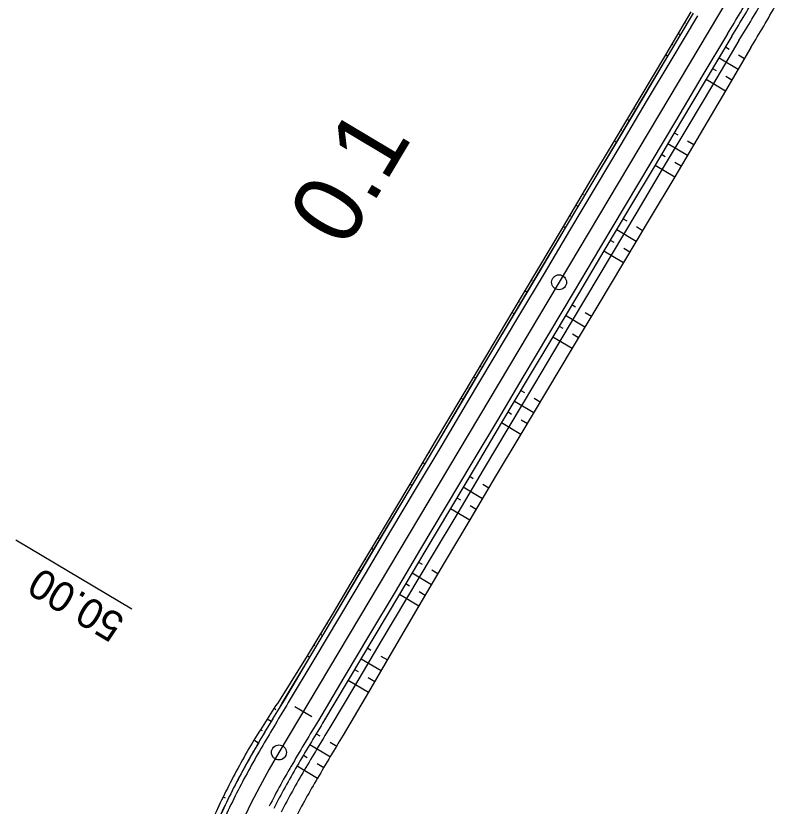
# Model space of a CAD drawing. Extents: x -481656 to -478728, y -1113199 to -1110710.
# Drawn here: x -479546.1 to -479469.9, y -1112507.3 to -1112428.2 of the extents above; entities that cross this region are included whole.
import ezdxf

# ---------------------------------------------------------------- set-up
doc = ezdxf.new("R2010")
doc.units = 0
for name, color, linetype in [('C1_HATCH_SLOPE_L', 7, 'Continuous'), ('C1_HATCH_SLOPE_R', 7, 'Continuous'), ('C1_HECTOMETRY', 7, 'Continuous'), ('C1_HLBODY', 7, 'Continuous'), ('C1_HRANA_TELESO', 7, 'Continuous'), ('C1_KORUNA', 7, 'Continuous'), ('C1_OSA', 7, 'Continuous'), ('C1_PRIKOP', 7, 'Continuous'), ('C1_STANICENI', 7, 'Continuous'), ('C1_VOZOVKA', 7, 'Continuous'), ('C1_ZPEVKRAJ', 7, 'Continuous')]:
    doc.layers.add(name, color=color, linetype=linetype)

msp = doc.modelspace()

# ---------------------------------------------------------------- linework, layer by layer
at = {"layer": 'C1_HATCH_SLOPE_L'}
for p, q in [((-479475.03, -1112431.371), (-479474.67, -1112431.586)), ((-479475.67, -1112432.445), (-479473.754, -1112433.587)), ((-479473.715, -1112432.154), (-479473.12, -1112432.509)), ((-479476.31, -1112433.519), (-479475.95, -1112433.734)), ((-479476.95, -1112434.593), (-479475.022, -1112435.741)), ((-479474.989, -1112434.306), (-479474.388, -1112434.664)), ((-479480.149, -1112439.962), (-479479.79, -1112440.176)), ((-479480.789, -1112441.036), (-479478.833, -1112442.201)), ((-479478.813, -1112440.758), (-479478.196, -1112441.126)), ((-479481.429, -1112442.109), (-479481.069, -1112442.324)), ((-479482.069, -1112443.183), (-479480.108, -1112444.352)), ((-479480.09, -1112442.908), (-479479.47, -1112443.277)), ((-479485.268, -1112448.552), (-479484.908, -1112448.766)), ((-479485.908, -1112449.626), (-479483.955, -1112450.79)), ((-479483.931, -1112449.349), (-479483.314, -1112449.717)), ((-479486.548, -1112450.7), (-479486.188, -1112450.914)), ((-479485.212, -1112451.496), (-479484.596, -1112451.863)), ((-479487.188, -1112451.774), (-479485.237, -1112452.936)), ((-479490.387, -1112457.143), (-479490.027, -1112457.357)), ((-479491.027, -1112458.217), (-479489.084, -1112459.375)), ((-479489.056, -1112457.936), (-479488.443, -1112458.301)), ((-479491.667, -1112459.29), (-479491.307, -1112459.504)), ((-479490.336, -1112460.084), (-479489.725, -1112460.448)), ((-479492.307, -1112460.364), (-479490.366, -1112461.521)), ((-479495.506, -1112465.733), (-479495.146, -1112465.948)), ((-479494.179, -1112466.524), (-479493.571, -1112466.886)), ((-479496.146, -1112466.807), (-479494.212, -1112467.959)), ((-479496.786, -1112467.881), (-479496.426, -1112468.096)), ((-479495.46, -1112468.671), (-479494.853, -1112469.032)), ((-479497.426, -1112468.955), (-479495.494, -1112470.106)), ((-479500.625, -1112474.324), (-479500.266, -1112474.538)), ((-479499.303, -1112475.112), (-479498.7, -1112475.471)), ((-479501.265, -1112475.397), (-479499.341, -1112476.544)), ((-479501.905, -1112476.471), (-479501.545, -1112476.686)), ((-479502.545, -1112477.545), (-479500.624, -1112478.69)), ((-479500.584, -1112477.258), (-479499.983, -1112477.617)), ((-479505.744, -1112482.914), (-479505.384, -1112483.128)), ((-479504.418, -1112483.704), (-479503.811, -1112484.066)), ((-479506.384, -1112483.988), (-479504.443, -1112485.145)), ((-479507.024, -1112485.062), (-479506.664, -1112485.276)), ((-479507.664, -1112486.135), (-479505.706, -1112487.302)), ((-479505.69, -1112485.856), (-479505.075, -1112486.223)), ((-479510.863, -1112491.505), (-479510.504, -1112491.719)), ((-479511.503, -1112492.578), (-479509.498, -1112493.773)), ((-479509.505, -1112492.314), (-479508.867, -1112492.694)), ((-479512.143, -1112493.652), (-479511.783, -1112493.866)), ((-479512.783, -1112494.726), (-479510.762, -1112495.93)), ((-479510.776, -1112494.466), (-479510.13, -1112494.852)), ((-479515.982, -1112500.095), (-479515.622, -1112500.31)), ((-479516.622, -1112501.169), (-479514.571, -1112502.391)), ((-479514.596, -1112500.921), (-479513.93, -1112501.318)), ((-479517.262, -1112502.243), (-479516.902, -1112502.457)), ((-479517.898, -1112503.311), (-479515.847, -1112504.525)), ((-479515.877, -1112503.068), (-479515.213, -1112503.464))]:
    msp.add_line(p, q, dxfattribs=at)
at = {"layer": 'C1_HATCH_SLOPE_R'}
for p, q in [((-479479.012, -1112428.999), (-479479.119, -1112428.935)), ((-479478.896, -1112429.068), (-479478.9, -1112429.066)), ((-479479.536, -1112430.142), (-479479.758, -1112430.009)), ((-479480.291, -1112431.146), (-479480.398, -1112431.083)), ((-479480.176, -1112431.215), (-479480.18, -1112431.212)), ((-479480.816, -1112432.289), (-479481.037, -1112432.157)), ((-479484.132, -1112437.588), (-479484.24, -1112437.524)), ((-479484.015, -1112437.658), (-479484.02, -1112437.656)), ((-479484.655, -1112438.732), (-479484.88, -1112438.598)), ((-479485.412, -1112439.736), (-479485.52, -1112439.672)), ((-479485.295, -1112439.806), (-479485.299, -1112439.804)), ((-479485.935, -1112440.88), (-479486.16, -1112440.745)), ((-479489.25, -1112446.18), (-479489.356, -1112446.116)), ((-479489.134, -1112446.249), (-479489.138, -1112446.246)), ((-479489.774, -1112447.323), (-479489.995, -1112447.19)), ((-479490.528, -1112448.328), (-479490.635, -1112448.264)), ((-479490.414, -1112448.396), (-479490.418, -1112448.394)), ((-479491.054, -1112449.47), (-479491.274, -1112449.338)), ((-479494.368, -1112454.77), (-479494.476, -1112454.706)), ((-479494.253, -1112454.839), (-479494.257, -1112454.836)), ((-479494.893, -1112455.913), (-479495.117, -1112455.78)), ((-479495.649, -1112456.918), (-479495.757, -1112456.853)), ((-479495.533, -1112456.987), (-479495.537, -1112456.984)), ((-479496.173, -1112458.061), (-479496.397, -1112457.927)), ((-479499.488, -1112463.36), (-479499.596, -1112463.296)), ((-479499.372, -1112463.43), (-479499.376, -1112463.427)), ((-479500.012, -1112464.503), (-479500.236, -1112464.37)), ((-479500.767, -1112465.508), (-479500.875, -1112465.444)), ((-479500.652, -1112465.577), (-479500.656, -1112465.574)), ((-479501.292, -1112466.651), (-479501.515, -1112466.518)), ((-479504.606, -1112471.952), (-479504.712, -1112471.888)), ((-479504.491, -1112472.02), (-479504.495, -1112472.018)), ((-479505.131, -1112473.094), (-479505.352, -1112472.962)), ((-479505.885, -1112474.1), (-479505.991, -1112474.036)), ((-479505.771, -1112474.168), (-479505.775, -1112474.166)), ((-479506.411, -1112475.241), (-479506.631, -1112475.11)), ((-479509.724, -1112480.542), (-479509.829, -1112480.48)), ((-479509.61, -1112480.611), (-479509.614, -1112480.608)), ((-479510.25, -1112481.684), (-479510.468, -1112481.554)), ((-479511.003, -1112482.69), (-479511.108, -1112482.628)), ((-479510.89, -1112482.758), (-479510.894, -1112482.756)), ((-479511.529, -1112483.832), (-479511.747, -1112483.702)), ((-479514.844, -1112489.132), (-479514.95, -1112489.069)), ((-479514.729, -1112489.201), (-479514.733, -1112489.198)), ((-479515.369, -1112490.275), (-479515.594, -1112490.14)), ((-479516.128, -1112491.277), (-479516.239, -1112491.211)), ((-479516.009, -1112491.349), (-479516.013, -1112491.346)), ((-479516.648, -1112492.422), (-479516.884, -1112492.282)), ((-479520.031, -1112497.682), (-479520.206, -1112497.578)), ((-479519.848, -1112497.791), (-479519.852, -1112497.788)), ((-479520.488, -1112498.865), (-479520.881, -1112498.631)), ((-479521.346, -1112499.808), (-479521.557, -1112499.683)), ((-479521.128, -1112499.939), (-479521.132, -1112499.936)), ((-479521.771, -1112501.019), (-479522.236, -1112500.744)), ((-479525.072, -1112506.548), (-479525.312, -1112506.431)), ((-479524.824, -1112506.671), (-479524.828, -1112506.668))]:
    msp.add_line(p, q, dxfattribs=at)
at = {"layer": 'C1_HECTOMETRY'}
msp.add_circle((-479491.68, -1112454.917), 0.75, dxfattribs=at)
at = {"layer": 'C1_HLBODY'}
msp.add_circle((-479519.714, -1112501.962), 0.75, dxfattribs=at)
at = {"layer": 'C1_HRANA_TELESO'}
for p, q in [((-479478.479, -1112427.861), (-479481.037, -1112432.157)), ((-479472.486, -1112431.432), (-479475.022, -1112435.741)), ((-479481.037, -1112432.157), (-479483.6, -1112436.451)), ((-479483.6, -1112436.451), (-479486.16, -1112440.745)), ((-479475.022, -1112435.741), (-479477.559, -1112440.05)), ((-479477.559, -1112440.05), (-479480.107, -1112444.352)), ((-479486.16, -1112440.745), (-479488.717, -1112445.042)), ((-479480.107, -1112444.352), (-479482.673, -1112448.643)), ((-479488.717, -1112445.042), (-479491.274, -1112449.338)), ((-479482.673, -1112448.643), (-479485.237, -1112452.936)), ((-479491.274, -1112449.338), (-479493.836, -1112453.632)), ((-479485.237, -1112452.936), (-479487.802, -1112457.228)), ((-479493.836, -1112453.632), (-479496.397, -1112457.927)), ((-479487.802, -1112457.228), (-479490.366, -1112461.521)), ((-479496.397, -1112457.927), (-479498.957, -1112462.222)), ((-479490.366, -1112461.521), (-479492.93, -1112465.813)), ((-479498.957, -1112462.222), (-479501.515, -1112466.518)), ((-479501.515, -1112466.518), (-479504.073, -1112470.814)), ((-479492.93, -1112465.813), (-479495.494, -1112470.106)), ((-479495.494, -1112470.106), (-479498.058, -1112474.398)), ((-479504.073, -1112470.814), (-479506.631, -1112475.11)), ((-479498.058, -1112474.398), (-479500.624, -1112478.69)), ((-479506.631, -1112475.11), (-479509.189, -1112479.406)), ((-479500.624, -1112478.69), (-479503.179, -1112482.987)), ((-479509.189, -1112479.406), (-479511.747, -1112483.702)), ((-479503.179, -1112482.987), (-479505.706, -1112487.302)), ((-479511.747, -1112483.702), (-479514.305, -1112487.999)), ((-479505.706, -1112487.302), (-479508.235, -1112491.616)), ((-479514.305, -1112487.999), (-479516.884, -1112492.282)), ((-479508.235, -1112491.616), (-479510.762, -1112495.93)), ((-479516.884, -1112492.282), (-479519.531, -1112496.525)), ((-479510.762, -1112495.93), (-479513.288, -1112500.245))]:
    msp.add_line(p, q, dxfattribs=at)
for centre, radius, start, end in [((-479602.418, -1112352.133), 152.219, 328.60374, 330.48953), ((-479311.798, -1112632.669), 248.371, 146.75999, 147.91596), ((-479320.518, -1112618.4), 226.099, 148.49464, 149.75825), ((-479451.013, -1112542.955), 82.792, 149.34614, 152.92713), ((-479451.002, -1112542.939), 82.794, 152.94056, 156.52155), ((-479451.06, -1112543.04), 75.371, 149.26903, 152.85003)]:
    msp.add_arc(centre, radius, start, end, dxfattribs=at)
at = {"layer": 'C1_KORUNA'}
for p, q in [((-479478.256, -1112427.994), (-479480.816, -1112432.289)), ((-479474.39, -1112430.298), (-479476.95, -1112434.593)), ((-479480.816, -1112432.289), (-479483.375, -1112436.584)), ((-479476.95, -1112434.593), (-479479.509, -1112438.888)), ((-479483.375, -1112436.584), (-479485.935, -1112440.88)), ((-479479.509, -1112438.888), (-479482.069, -1112443.183)), ((-479485.935, -1112440.88), (-479488.494, -1112445.175)), ((-479482.069, -1112443.183), (-479484.628, -1112447.478)), ((-479488.494, -1112445.175), (-479491.054, -1112449.47)), ((-479484.628, -1112447.478), (-479487.188, -1112451.774)), ((-479491.054, -1112449.47), (-479493.613, -1112453.765)), ((-479487.188, -1112451.774), (-479489.747, -1112456.069)), ((-479493.613, -1112453.765), (-479496.173, -1112458.061)), ((-479489.747, -1112456.069), (-479492.307, -1112460.364)), ((-479496.173, -1112458.061), (-479498.732, -1112462.356)), ((-479492.307, -1112460.364), (-479494.866, -1112464.659)), ((-479498.732, -1112462.356), (-479501.292, -1112466.651)), ((-479494.866, -1112464.659), (-479497.426, -1112468.955)), ((-479501.292, -1112466.651), (-479503.851, -1112470.946)), ((-479497.426, -1112468.955), (-479499.985, -1112473.25)), ((-479503.851, -1112470.946), (-479506.411, -1112475.241)), ((-479499.985, -1112473.25), (-479502.545, -1112477.545)), ((-479506.411, -1112475.241), (-479508.97, -1112479.537)), ((-479502.545, -1112477.545), (-479505.104, -1112481.84)), ((-479508.97, -1112479.537), (-479511.529, -1112483.832)), ((-479505.104, -1112481.84), (-479507.664, -1112486.135)), ((-479511.529, -1112483.832), (-479514.089, -1112488.127)), ((-479507.664, -1112486.135), (-479510.223, -1112490.431)), ((-479514.089, -1112488.127), (-479516.648, -1112492.422)), ((-479510.223, -1112490.431), (-479512.783, -1112494.726)), ((-479516.648, -1112492.422), (-479519.208, -1112496.718)), ((-479512.783, -1112494.726), (-479515.342, -1112499.021))]:
    msp.add_line(p, q, dxfattribs=at)
for centre, radius, start, end in [((-479602.926, -1112350.816), 151.125, 328.26905, 330.16664), ((-479308.522, -1112625.158), 246.75, 148.6324, 149.79497), ((-479316.251, -1112620.546), 233.25, 148.60017, 149.82677), ((-479450.99, -1112542.914), 82.25, 149.37844, 152.95943), ((-479450.99, -1112542.914), 77.75, 149.37844, 152.95943), ((-479450.99, -1112542.914), 82.25, 152.95943, 156.54042)]:
    msp.add_arc(centre, radius, start, end, dxfattribs=at)
at = {"layer": 'C1_OSA'}
msp.add_line((-479474.099, -1112425.413), (-479519.714, -1112501.962), dxfattribs=at)
msp.add_arc((-479450.99, -1112542.914), 80, 149.2096, 193.42692, dxfattribs=at)
at = {"layer": 'C1_PRIKOP'}
for p, q in [((-479478.265, -1112427.989), (-479480.824, -1112432.284)), ((-479473.671, -1112430.726), (-479476.23, -1112435.022)), ((-479480.824, -1112432.284), (-479483.384, -1112436.579)), ((-479476.23, -1112435.022), (-479478.79, -1112439.317)), ((-479483.384, -1112436.579), (-479485.943, -1112440.875)), ((-479478.79, -1112439.317), (-479481.349, -1112443.612)), ((-479485.943, -1112440.875), (-479488.503, -1112445.17)), ((-479481.349, -1112443.612), (-479483.909, -1112447.907)), ((-479488.503, -1112445.17), (-479491.062, -1112449.465)), ((-479483.909, -1112447.907), (-479486.468, -1112452.202)), ((-479491.062, -1112449.465), (-479493.622, -1112453.76)), ((-479486.468, -1112452.202), (-479489.028, -1112456.498)), ((-479493.622, -1112453.76), (-479496.181, -1112458.055)), ((-479489.028, -1112456.498), (-479491.587, -1112460.793)), ((-479496.181, -1112458.055), (-479498.741, -1112462.351)), ((-479491.587, -1112460.793), (-479494.147, -1112465.088)), ((-479498.741, -1112462.351), (-479501.3, -1112466.646)), ((-479494.147, -1112465.088), (-479496.706, -1112469.383)), ((-479501.3, -1112466.646), (-479503.86, -1112470.941)), ((-479496.706, -1112469.383), (-479499.266, -1112473.679)), ((-479503.86, -1112470.941), (-479506.419, -1112475.236)), ((-479499.266, -1112473.679), (-479501.825, -1112477.974)), ((-479506.419, -1112475.236), (-479508.979, -1112479.532)), ((-479501.825, -1112477.974), (-479504.385, -1112482.269)), ((-479508.979, -1112479.532), (-479511.538, -1112483.827)), ((-479504.385, -1112482.269), (-479506.944, -1112486.564)), ((-479511.538, -1112483.827), (-479514.098, -1112488.122)), ((-479506.944, -1112486.564), (-479509.504, -1112490.86)), ((-479514.098, -1112488.122), (-479516.657, -1112492.417)), ((-479509.504, -1112490.86), (-479512.063, -1112495.155)), ((-479516.657, -1112492.417), (-479519.217, -1112496.713)), ((-479512.063, -1112495.155), (-479514.623, -1112499.45))]:
    msp.add_line(p, q, dxfattribs=at)
for centre, radius, start, end in [((-479602.566, -1112351.03), 151.544, 328.27135, 330.16439), ((-479308.504, -1112625.168), 246.78, 148.63247, 149.7949), ((-479317.69, -1112619.688), 230.737, 148.59376, 149.83311), ((-479450.99, -1112542.914), 82.26, 149.37844, 152.95943), ((-479450.99, -1112542.914), 76.912, 149.37844, 152.95943), ((-479450.99, -1112542.914), 82.26, 152.95943, 156.54042)]:
    msp.add_arc(centre, radius, start, end, dxfattribs=at)
at = {"layer": 'C1_STANICENI'}
for p, q in [((-479534.456, -1112487.631), (-479546.053, -1112480.721)), ((-479518.134, -1112497.358), (-479516.416, -1112498.381))]:
    msp.add_line(p, q, dxfattribs=at)
at = {"layer": 'C1_VOZOVKA'}
for p, q in [((-479477.827, -1112428.25), (-479480.386, -1112432.545)), ((-479474.82, -1112430.042), (-479477.379, -1112434.337)), ((-479480.386, -1112432.545), (-479482.946, -1112436.84)), ((-479477.379, -1112434.337), (-479479.939, -1112438.632)), ((-479482.946, -1112436.84), (-479485.505, -1112441.136)), ((-479479.939, -1112438.632), (-479482.498, -1112442.927)), ((-479485.505, -1112441.136), (-479488.065, -1112445.431)), ((-479482.498, -1112442.927), (-479485.058, -1112447.222)), ((-479488.065, -1112445.431), (-479490.624, -1112449.726)), ((-479485.058, -1112447.222), (-479487.617, -1112451.518)), ((-479490.624, -1112449.726), (-479493.184, -1112454.021)), ((-479487.617, -1112451.518), (-479490.177, -1112455.813)), ((-479493.184, -1112454.021), (-479495.743, -1112458.317)), ((-479490.177, -1112455.813), (-479492.736, -1112460.108)), ((-479495.743, -1112458.317), (-479498.302, -1112462.612)), ((-479492.736, -1112460.108), (-479495.296, -1112464.403)), ((-479498.302, -1112462.612), (-479500.862, -1112466.907)), ((-479495.296, -1112464.403), (-479497.855, -1112468.699)), ((-479500.862, -1112466.907), (-479503.421, -1112471.202)), ((-479497.855, -1112468.699), (-479500.415, -1112472.994)), ((-479503.421, -1112471.202), (-479505.981, -1112475.497)), ((-479500.415, -1112472.994), (-479502.974, -1112477.289)), ((-479505.981, -1112475.497), (-479508.54, -1112479.793)), ((-479502.974, -1112477.289), (-479505.534, -1112481.584)), ((-479508.54, -1112479.793), (-479511.1, -1112484.088)), ((-479505.534, -1112481.584), (-479508.093, -1112485.88)), ((-479511.1, -1112484.088), (-479513.659, -1112488.383)), ((-479508.093, -1112485.88), (-479510.653, -1112490.175)), ((-479513.659, -1112488.383), (-479516.219, -1112492.678)), ((-479510.653, -1112490.175), (-479513.212, -1112494.47)), ((-479516.219, -1112492.678), (-479518.778, -1112496.974)), ((-479513.212, -1112494.47), (-479515.772, -1112498.765))]:
    msp.add_line(p, q, dxfattribs=at)
for centre, radius, start, end in [((-479603.141, -1112350.689), 150.875, 328.26768, 330.168), ((-479309.38, -1112624.645), 245.25, 148.62899, 149.79833), ((-479315.392, -1112621.058), 234.75, 148.60394, 149.82306), ((-479450.99, -1112542.914), 81.75, 149.37844, 152.95943), ((-479450.99, -1112542.914), 78.25, 149.37844, 152.95943), ((-479450.99, -1112542.914), 81.75, 152.95943, 156.54042)]:
    msp.add_arc(centre, radius, start, end, dxfattribs=at)
at = {"layer": 'C1_ZPEVKRAJ'}
for p, q in [((-479477.827, -1112428.25), (-479480.386, -1112432.545)), ((-479474.82, -1112430.042), (-479477.379, -1112434.337)), ((-479480.386, -1112432.545), (-479482.946, -1112436.84)), ((-479477.379, -1112434.337), (-479479.939, -1112438.632)), ((-479482.946, -1112436.84), (-479485.505, -1112441.136)), ((-479479.939, -1112438.632), (-479482.498, -1112442.927)), ((-479485.505, -1112441.136), (-479488.065, -1112445.431)), ((-479482.498, -1112442.927), (-479485.058, -1112447.222)), ((-479488.065, -1112445.431), (-479490.624, -1112449.726)), ((-479485.058, -1112447.222), (-479487.617, -1112451.518)), ((-479490.624, -1112449.726), (-479493.184, -1112454.021)), ((-479487.617, -1112451.518), (-479490.177, -1112455.813)), ((-479493.184, -1112454.021), (-479495.743, -1112458.317)), ((-479490.177, -1112455.813), (-479492.736, -1112460.108)), ((-479495.743, -1112458.317), (-479498.302, -1112462.612)), ((-479492.736, -1112460.108), (-479495.296, -1112464.403)), ((-479498.302, -1112462.612), (-479500.862, -1112466.907)), ((-479495.296, -1112464.403), (-479497.855, -1112468.699)), ((-479500.862, -1112466.907), (-479503.421, -1112471.202)), ((-479497.855, -1112468.699), (-479500.415, -1112472.994)), ((-479503.421, -1112471.202), (-479505.981, -1112475.497)), ((-479500.415, -1112472.994), (-479502.974, -1112477.289)), ((-479505.981, -1112475.497), (-479508.54, -1112479.793)), ((-479502.974, -1112477.289), (-479505.534, -1112481.584)), ((-479508.54, -1112479.793), (-479511.1, -1112484.088)), ((-479505.534, -1112481.584), (-479508.093, -1112485.88)), ((-479511.1, -1112484.088), (-479513.659, -1112488.383)), ((-479508.093, -1112485.88), (-479510.653, -1112490.175)), ((-479513.659, -1112488.383), (-479516.219, -1112492.678)), ((-479510.653, -1112490.175), (-479513.212, -1112494.47)), ((-479516.219, -1112492.678), (-479518.778, -1112496.974)), ((-479513.212, -1112494.47), (-479515.772, -1112498.765))]:
    msp.add_line(p, q, dxfattribs=at)
for centre, radius, start, end in [((-479603.141, -1112350.689), 150.875, 328.26768, 330.168), ((-479309.38, -1112624.645), 245.25, 148.62899, 149.79833), ((-479315.392, -1112621.058), 234.75, 148.60394, 149.82306), ((-479450.99, -1112542.914), 81.75, 149.37844, 152.95943), ((-479450.99, -1112542.914), 78.25, 149.37844, 152.95943), ((-479450.99, -1112542.914), 81.75, 152.95943, 156.54042)]:
    msp.add_arc(centre, radius, start, end, dxfattribs=at)

# ---------------------------------------------------------------- texts
at = {"layer": 'C1_HECTOMETRY'}
msp.add_text('0.1', height=7, rotation=59.16397, dxfattribs=at).set_placement((-479513.047, -1112451.691))
at = {"layer": 'C1_STANICENI'}
msp.add_text('50.00', height=3, rotation=149.2096, dxfattribs=at).set_placement((-479534.967, -1112488.491))

doc.saveas('drawing.dxf')
